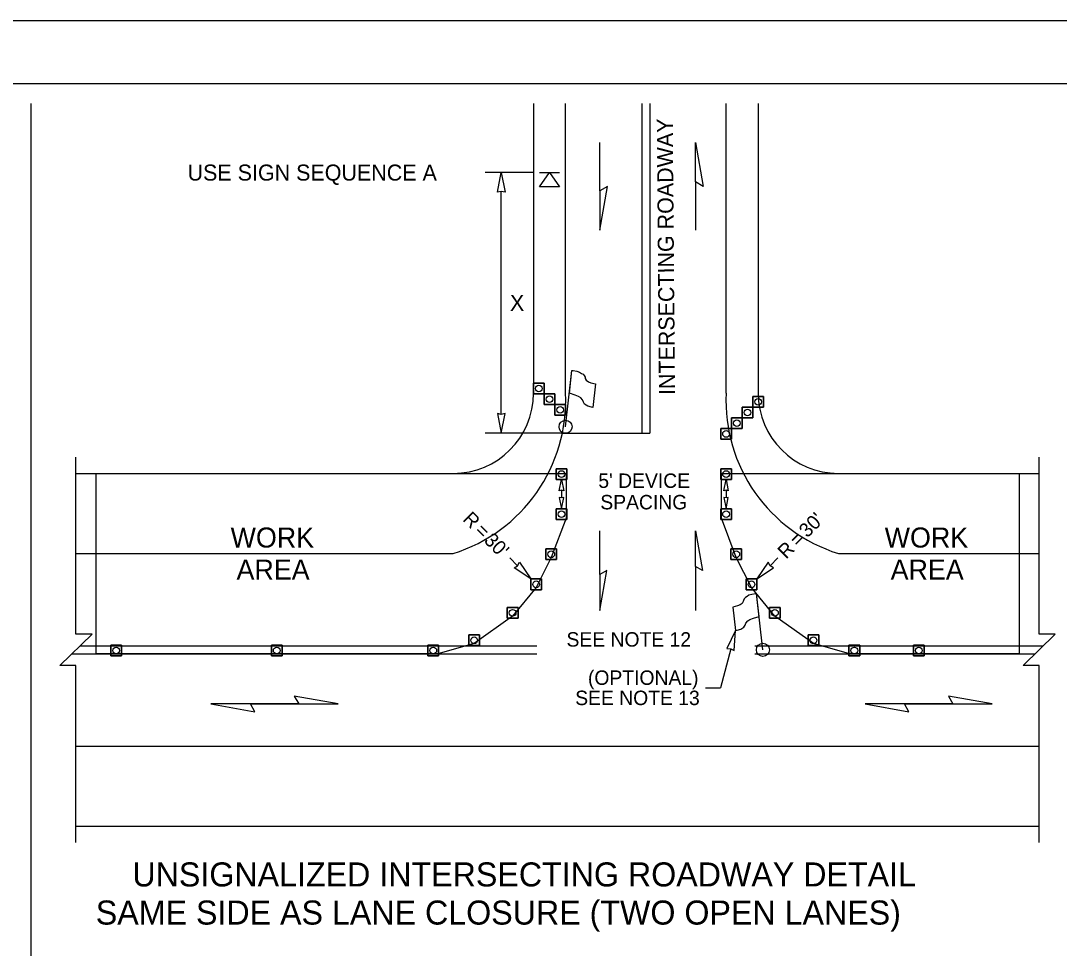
# Model space of a CAD drawing. Extents: x 99999.1 to 100095.7, y 99995 to 100010.7.
# Drawn here: x 100025.2 to 100030.38, y 100006.06 to 100010.69 of the extents above; entities that cross this region are included whole.
import ezdxf

# ---------------------------------------------------------------- set-up
doc = ezdxf.new("R2010")
doc.units = 0
for name, color, linetype in [('RD_ED_ShoulderPavedEdge', 7, 'Continuous'), ('RD_MK_LineDblYellowCenter', 7, 'Continuous'), ('RD_MK_LineEdgeWhite', 7, 'Continuous'), ('RD_MK_LineStop', 7, 'Continuous'), ('SH_DE_DetailBody1Text', 7, 'Continuous'), ('SH_DE_DetailHeading2Text', 7, 'Continuous'), ('SH_GI_PlotLimits', 7, 'Continuous'), ('SH_GI_SheetBorder', 7, 'Continuous'), ('TR_WZ_FlaggingStation', 7, 'Continuous'), ('TR_WZ_PortableSignMountBlk-Org', 7, 'Continuous'), ('TR_WZ_TrafficCone', 7, 'Continuous'), ('TR_WZ_WorkAreaLabel', 7, 'Continuous'), ('TR_WZ_WorkZoneDetails', 7, 'Continuous'), ('TR_WZ_WorkZoneTextCurrent', 7, 'Continuous')]:
    doc.layers.add(name, color=color, linetype=linetype)

msp = doc.modelspace()

# ---------------------------------------------------------------- linework, layer by layer
at = {"layer": 'RD_ED_ShoulderPavedEdge'}
for p, q in [((100025.475, 100008.4304), (100027.355, 100008.4304)), ((100029.275, 100008.4304), (100030.275, 100008.4304)), ((100025.475, 100006.6704), (100030.275, 100006.6704))]:
    msp.add_line(p, q, dxfattribs=at)
for points in [[(100027.755, 100010.275), (100027.755, 100008.8304)], [(100028.875, 100010.275), (100028.875, 100008.8304)]]:
    msp.add_lwpolyline(points, dxfattribs=at)
for centre, start, end in [((100027.355, 100008.8304), 270, 0), ((100029.275, 100008.8304), 180, 270)]:
    msp.add_arc(centre, 0.4, start, end, dxfattribs=at)
at = {"layer": 'RD_MK_LineDblYellowCenter'}
for p, q in [((100028.295, 100010.275), (100028.295, 100008.6304)), ((100028.335, 100010.275), (100028.335, 100008.6304)), ((100025.4957, 100007.5704), (100027.7712, 100007.5704)), ((100028.8588, 100007.5704), (100030.2957, 100007.5704)), ((100025.4543, 100007.5305), (100027.7712, 100007.5305)), ((100028.8588, 100007.5305), (100030.2543, 100007.5305))]:
    msp.add_line(p, q, dxfattribs=at)
at = {"layer": 'RD_MK_LineEdgeWhite'}
for p, q in [((100027.915, 100008.8304), (100027.915, 100010.275)), ((100028.715, 100008.8304), (100028.715, 100010.275)), ((100025.475, 100008.0305), (100027.355, 100008.0305)), ((100029.275, 100008.0305), (100030.275, 100008.0305)), ((100025.475, 100007.0704), (100030.275, 100007.0704))]:
    msp.add_line(p, q, dxfattribs=at)
for centre, start, end in [((100027.1158, 100008.7939), 287.3948, 2.6212), ((100029.5142, 100008.7939), 177.3788, 252.6052)]:
    msp.add_arc(centre, 0.8, start, end, dxfattribs=at)
at = {"layer": 'RD_MK_LineStop'}
msp.add_line((100027.899, 100008.6304), (100028.335, 100008.6304), dxfattribs=at)
at = {"layer": 'SH_GI_PlotLimits'}
msp.add_lwpolyline([(100019.0625, 99999.6875), (100036.0625, 99999.6875), (100036.0625, 100010.6875), (100019.0625, 100010.6875)], close=True, dxfattribs=at)
at = {"layer": 'SH_GI_SheetBorder'}
msp.add_line((100020, 100010.375), (100035.75, 100010.375), dxfattribs=at)
at = {"layer": 'TR_WZ_FlaggingStation'}
for p, q in [((100027.915, 100008.6629), (100027.9471, 100008.9439)), ((100027.934, 100008.8299), (100027.9471, 100008.9442)), ((100028.065, 100008.8764), (100028.0517, 100008.7592)), ((100027.934, 100008.8299), (100027.934, 100008.8299)), ((100028.8797, 100007.7174), (100028.8667, 100007.8317)), ((100028.8988, 100007.5504), (100028.8667, 100007.8314)), ((100028.7487, 100007.7639), (100028.762, 100007.6467)), ((100028.8797, 100007.7174), (100028.8797, 100007.7174))]:
    msp.add_line(p, q, dxfattribs=at)
for points in [[(100027.9471, 100008.9442), (100027.9528, 100008.9429), (100027.9707, 100008.9395), (100027.9845, 100008.9353), (100027.9942, 100008.9292), (100028.0027, 100008.9245), (100028.0084, 100008.9177), (100028.0126, 100008.9098), (100028.0131, 100008.9037), (100028.0185, 100008.8944), (100028.0293, 100008.887), (100028.0417, 100008.8818), (100028.065, 100008.8764)], [(100028.0517, 100008.7592), (100028.0436, 100008.7606), (100028.0259, 100008.7653), (100028.0103, 100008.7758), (100028.0037, 100008.7863), (100027.9998, 100008.7966), (100027.9907, 100008.8075), (100027.9798, 100008.8137), (100027.9624, 100008.8208), (100027.934, 100008.8299)], [(100028.8667, 100007.8317), (100028.8609, 100007.8304), (100028.8431, 100007.827), (100028.8293, 100007.8228), (100028.8196, 100007.8167), (100028.8111, 100007.812), (100028.8054, 100007.8052), (100028.8012, 100007.7973), (100028.8006, 100007.7912), (100028.7953, 100007.7819), (100028.7845, 100007.7745), (100028.7721, 100007.7693), (100028.7487, 100007.7639)], [(100028.762, 100007.6467), (100028.7702, 100007.6481), (100028.7879, 100007.6528), (100028.8035, 100007.6633), (100028.81, 100007.6738), (100028.814, 100007.6841), (100028.823, 100007.695), (100028.834, 100007.7012), (100028.8514, 100007.7083), (100028.8797, 100007.7174)]]:
    msp.add_lwpolyline(points, dxfattribs=at)
for centre in [(100027.915, 100008.6629), (100028.8988, 100007.5504)]:
    msp.add_circle(centre, 0.0325, dxfattribs=at)
at = {"layer": 'TR_WZ_PortableSignMountBlk-Org'}
msp.add_line((100027.785, 100009.9304), (100027.885, 100009.9304), dxfattribs=at)
msp.add_lwpolyline([(100027.8349, 100009.9304), (100027.885, 100009.8586), (100027.785, 100009.8586)], close=True, dxfattribs=at)
at = {"layer": 'TR_WZ_TrafficCone'}
for points in [[(100027.8083, 100008.8803), (100027.8083, 100008.827), (100027.755, 100008.827), (100027.755, 100008.8803), (100027.8083, 100008.8803)], [(100027.755, 100008.8803), (100027.755, 100008.827), (100027.8083, 100008.827), (100027.8083, 100008.8803), (100027.755, 100008.8803)], [(100027.8617, 100008.827), (100027.8617, 100008.7736), (100027.8083, 100008.7736), (100027.8083, 100008.827), (100027.8617, 100008.827)], [(100027.8083, 100008.827), (100027.8083, 100008.7736), (100027.8617, 100008.7736), (100027.8617, 100008.827), (100027.8083, 100008.827)], [(100028.9016, 100008.8138), (100028.8483, 100008.8138), (100028.8483, 100008.7605), (100028.9016, 100008.7605), (100028.9016, 100008.8138)], [(100028.9016, 100008.7605), (100028.8483, 100008.7605), (100028.8483, 100008.8138), (100028.9016, 100008.8138), (100028.9016, 100008.7605)], [(100027.915, 100008.7736), (100027.915, 100008.7203), (100027.8617, 100008.7203), (100027.8617, 100008.7736), (100027.915, 100008.7736)], [(100027.8617, 100008.7736), (100027.8617, 100008.7203), (100027.915, 100008.7203), (100027.915, 100008.7736), (100027.8617, 100008.7736)], [(100028.8483, 100008.7605), (100028.795, 100008.7605), (100028.795, 100008.7071), (100028.8483, 100008.7071), (100028.8483, 100008.7605)], [(100028.8483, 100008.7071), (100028.795, 100008.7071), (100028.795, 100008.7605), (100028.8483, 100008.7605), (100028.8483, 100008.7071)], [(100028.795, 100008.7071), (100028.7416, 100008.7071), (100028.7416, 100008.6538), (100028.795, 100008.6538), (100028.795, 100008.7071)], [(100028.795, 100008.6538), (100028.7416, 100008.6538), (100028.7416, 100008.7071), (100028.795, 100008.7071), (100028.795, 100008.6538)], [(100028.7416, 100008.6538), (100028.6883, 100008.6538), (100028.6883, 100008.6005), (100028.7416, 100008.6005), (100028.7416, 100008.6538)], [(100028.7416, 100008.6005), (100028.6883, 100008.6005), (100028.6883, 100008.6538), (100028.7416, 100008.6538), (100028.7416, 100008.6005)], [(100027.8684, 100008.4538), (100027.9217, 100008.4538), (100027.9217, 100008.4005), (100027.8684, 100008.4005), (100027.8684, 100008.4538)], [(100027.8684, 100008.4005), (100027.9217, 100008.4005), (100027.9217, 100008.4538), (100027.8684, 100008.4538), (100027.8684, 100008.4005)], [(100028.7416, 100008.4538), (100028.6883, 100008.4538), (100028.6883, 100008.4005), (100028.7416, 100008.4005), (100028.7416, 100008.4538)], [(100028.7416, 100008.4005), (100028.6883, 100008.4005), (100028.6883, 100008.4538), (100028.7416, 100008.4538), (100028.7416, 100008.4005)], [(100027.8684, 100008.2538), (100027.9217, 100008.2538), (100027.9217, 100008.2005), (100027.8684, 100008.2005), (100027.8684, 100008.2538)], [(100027.8684, 100008.2005), (100027.9217, 100008.2005), (100027.9217, 100008.2538), (100027.8684, 100008.2538), (100027.8684, 100008.2005)], [(100028.7416, 100008.2538), (100028.6883, 100008.2538), (100028.6883, 100008.2005), (100028.7416, 100008.2005), (100028.7416, 100008.2538)], [(100028.7416, 100008.2005), (100028.6883, 100008.2005), (100028.6883, 100008.2538), (100028.7416, 100008.2538), (100028.7416, 100008.2005)], [(100027.8173, 100008.0538), (100027.8707, 100008.0538), (100027.8707, 100008.0005), (100027.8173, 100008.0005), (100027.8173, 100008.0538)], [(100027.8173, 100008.0005), (100027.8707, 100008.0005), (100027.8707, 100008.0538), (100027.8173, 100008.0538), (100027.8173, 100008.0005)], [(100028.7927, 100008.0538), (100028.7393, 100008.0538), (100028.7393, 100008.0005), (100028.7927, 100008.0005), (100028.7927, 100008.0538)], [(100028.7927, 100008.0005), (100028.7393, 100008.0005), (100028.7393, 100008.0538), (100028.7927, 100008.0538), (100028.7927, 100008.0005)], [(100027.7417, 100007.9038), (100027.795, 100007.9038), (100027.795, 100007.8505), (100027.7417, 100007.8505), (100027.7417, 100007.9038)], [(100027.7417, 100007.8505), (100027.795, 100007.8505), (100027.795, 100007.9038), (100027.7417, 100007.9038), (100027.7417, 100007.8505)], [(100028.8683, 100007.9038), (100028.815, 100007.9038), (100028.815, 100007.8505), (100028.8683, 100007.8505), (100028.8683, 100007.9038)], [(100028.8683, 100007.8505), (100028.815, 100007.8505), (100028.815, 100007.9038), (100028.8683, 100007.9038), (100028.8683, 100007.8505)], [(100027.6247, 100007.7615), (100027.6781, 100007.7615), (100027.6781, 100007.7082), (100027.6247, 100007.7082), (100027.6247, 100007.7615)], [(100027.6247, 100007.7082), (100027.6781, 100007.7082), (100027.6781, 100007.7615), (100027.6247, 100007.7615), (100027.6247, 100007.7082)], [(100028.9853, 100007.7615), (100028.9319, 100007.7615), (100028.9319, 100007.7082), (100028.9853, 100007.7082), (100028.9853, 100007.7615)], [(100028.9853, 100007.7082), (100028.9319, 100007.7082), (100028.9319, 100007.7615), (100028.9853, 100007.7615), (100028.9853, 100007.7082)], [(100027.433, 100007.6247), (100027.4864, 100007.6247), (100027.4864, 100007.5714), (100027.433, 100007.5714), (100027.433, 100007.6247)], [(100027.433, 100007.5714), (100027.4864, 100007.5714), (100027.4864, 100007.6247), (100027.433, 100007.6247), (100027.433, 100007.5714)], [(100029.177, 100007.6247), (100029.1236, 100007.6247), (100029.1236, 100007.5714), (100029.177, 100007.5714), (100029.177, 100007.6247)], [(100029.177, 100007.5714), (100029.1236, 100007.5714), (100029.1236, 100007.6247), (100029.177, 100007.6247), (100029.177, 100007.5714)], [(100025.649, 100007.5738), (100025.7024, 100007.5738), (100025.7024, 100007.5205), (100025.649, 100007.5205), (100025.649, 100007.5738)], [(100025.649, 100007.5205), (100025.7024, 100007.5205), (100025.7024, 100007.5738), (100025.649, 100007.5738), (100025.649, 100007.5205)], [(100026.449, 100007.5738), (100026.5024, 100007.5738), (100026.5024, 100007.5205), (100026.449, 100007.5205), (100026.449, 100007.5738)], [(100026.449, 100007.5205), (100026.5024, 100007.5205), (100026.5024, 100007.5738), (100026.449, 100007.5738), (100026.449, 100007.5205)], [(100027.229, 100007.5738), (100027.2824, 100007.5738), (100027.2824, 100007.5205), (100027.229, 100007.5205), (100027.229, 100007.5738)], [(100027.229, 100007.5205), (100027.2824, 100007.5205), (100027.2824, 100007.5738), (100027.229, 100007.5738), (100027.229, 100007.5205)], [(100029.381, 100007.5738), (100029.3276, 100007.5738), (100029.3276, 100007.5205), (100029.381, 100007.5205), (100029.381, 100007.5738)], [(100029.381, 100007.5205), (100029.3276, 100007.5205), (100029.3276, 100007.5738), (100029.381, 100007.5738), (100029.381, 100007.5205)], [(100029.649, 100007.5738), (100029.7024, 100007.5738), (100029.7024, 100007.5205), (100029.649, 100007.5205), (100029.649, 100007.5738)], [(100029.649, 100007.5205), (100029.7024, 100007.5205), (100029.7024, 100007.5738), (100029.649, 100007.5738), (100029.649, 100007.5205)]]:
    msp.add_lwpolyline(points, dxfattribs=at)
for centre in [(100027.7817, 100008.8536), (100027.835, 100008.8003), (100028.875, 100008.7871), (100027.8883, 100008.747), (100028.8216, 100008.7338), (100028.7683, 100008.6805), (100028.715, 100008.6271), (100027.895, 100008.4271), (100028.715, 100008.4271), (100027.895, 100008.2271), (100028.715, 100008.2271), (100027.844, 100008.0271), (100028.766, 100008.0271), (100027.7683, 100007.8771), (100028.8417, 100007.8771), (100027.6514, 100007.7349), (100028.9586, 100007.7349), (100027.4597, 100007.598), (100029.1503, 100007.598), (100025.6757, 100007.5471), (100026.4757, 100007.5471), (100027.2557, 100007.5471), (100029.3543, 100007.5471), (100029.6757, 100007.5471)]:
    msp.add_circle(centre, 0.0167, dxfattribs=at)
at = {"layer": 'TR_WZ_WorkZoneDetails'}
for p, q in [((100025.25, 100010.275), (100025.25, 100001.6859)), ((100028.0855, 100009.8393), (100028.0855, 100010.0804)), ((100027.755, 100009.9304), (100027.515, 100009.9304)), ((100028.5627, 100009.8839), (100028.5627, 100009.6428)), ((100027.595, 100008.7242), (100027.595, 100009.8367)), ((100027.899, 100008.6304), (100027.515, 100008.6304)), ((100027.8951, 100008.3459), (100027.8951, 100008.3083)), ((100028.715, 100008.3459), (100028.715, 100008.3083)), ((100028.0855, 100007.9255), (100028.0855, 100008.1445)), ((100027.6754, 100007.9701), (100027.637, 100008.0085)), ((100028.9346, 100007.9701), (100028.973, 100008.0085)), ((100028.5627, 100007.9659), (100028.5627, 100007.7469)), ((100028.7385, 100007.556), (100028.688, 100007.3613)), ((100028.6118, 100007.3613), (100028.688, 100007.3613)), ((100026.3444, 100007.2805), (100026.5856, 100007.2805)), ((100026.5856, 100007.2805), (100026.3444, 100007.2805)), ((100029.6043, 100007.2805), (100029.8454, 100007.2805)), ((100029.8454, 100007.2805), (100029.6043, 100007.2805))]:
    msp.add_line(p, q, dxfattribs=at)
for points in [[(100028.5627, 100010.0804), (100028.6013, 100009.8616), (100028.5627, 100009.8839)], [(100027.595, 100009.9304), (100027.6143, 100009.8322), (100027.595, 100009.8367), (100027.5757, 100009.8322)], [(100028.0855, 100009.6428), (100028.124, 100009.8616), (100028.0855, 100009.8393)], [(100027.595, 100008.6304), (100027.6143, 100008.7287), (100027.595, 100008.7242), (100027.5757, 100008.7287)], [(100027.9183, 100008.4304), (100027.9183, 100008.2071), (100027.844, 100008.0105), (100027.7683, 100007.8605), (100027.7683, 100007.8605), (100027.7683, 100007.8605), (100027.6514, 100007.7182), (100027.6514, 100007.7182), (100027.6514, 100007.7182), (100027.4597, 100007.5814), (100027.279, 100007.5305), (100026.499, 100007.5305), (100025.699, 100007.5305), (100025.575, 100007.5305), (100025.575, 100008.4304)], [(100027.895, 100008.4005), (100027.9063, 100008.3433), (100027.895, 100008.3459), (100027.8838, 100008.3433)], [(100030.175, 100008.4304), (100030.175, 100007.5305), (100029.699, 100007.5305), (100029.6523, 100007.5305), (100029.6523, 100007.5305), (100029.6523, 100007.5305), (100029.331, 100007.5305), (100029.331, 100007.5305), (100029.331, 100007.5305), (100029.1503, 100007.5814), (100028.9586, 100007.7182), (100028.8417, 100007.8605), (100028.766, 100008.0105), (100028.6917, 100008.2071), (100028.6917, 100008.4304)], [(100028.7149, 100008.4005), (100028.7261, 100008.3433), (100028.7149, 100008.3459), (100028.7037, 100008.3433)], [(100027.8951, 100008.2538), (100027.9063, 100008.3109), (100027.8951, 100008.3083), (100027.8839, 100008.3109)], [(100028.715, 100008.2538), (100028.7262, 100008.3109), (100028.715, 100008.3083), (100028.7037, 100008.3109)], [(100028.5627, 100008.1445), (100028.5977, 100007.9457), (100028.5627, 100007.9659)], [(100027.7417, 100007.9038), (100027.6586, 100007.9597), (100027.6754, 100007.9701), (100027.6858, 100007.987)], [(100028.8683, 100007.9038), (100028.9514, 100007.9597), (100028.9346, 100007.9701), (100028.9242, 100007.987)], [(100028.0855, 100007.7469), (100028.1205, 100007.9457), (100028.0855, 100007.9255)], [(100028.762, 100007.6467), (100028.7187, 100007.5564), (100028.7385, 100007.556), (100028.7561, 100007.5467)], [(100026.7821, 100007.2805), (100026.5633, 100007.319), (100026.5856, 100007.2805)], [(100030.0419, 100007.2805), (100029.8231, 100007.319), (100029.8454, 100007.2805)], [(100026.1479, 100007.2805), (100026.3667, 100007.2419), (100026.3444, 100007.2805)], [(100029.4077, 100007.2805), (100029.6265, 100007.2419), (100029.6043, 100007.2805)]]:
    msp.add_lwpolyline(points, close=True, dxfattribs=at)
for points in [[(100025.475, 100006.5904), (100025.475, 100007.473), (100025.395, 100007.473), (100025.555, 100007.6279), (100025.475, 100007.6279), (100025.475, 100008.5105)], [(100030.275, 100006.5904), (100030.275, 100007.473), (100030.195, 100007.473), (100030.355, 100007.6279), (100030.275, 100007.6279), (100030.275, 100008.5105)]]:
    msp.add_lwpolyline(points, dxfattribs=at)

# ---------------------------------------------------------------- texts
at = {"layer": 'SH_DE_DetailBody1Text'}
msp.add_text('INTERSECTING ROADWAY', height=0.08, rotation=90.4626, dxfattribs=at).set_placement((100028.4607, 100008.8214))
at = {"layer": 'SH_DE_DetailHeading2Text'}
for s, p in [('UNSIGNALIZED INTERSECTING ROADWAY DETAIL', (100025.7563, 100006.3705)), ('SAME SIDE AS LANE CLOSURE (TWO OPEN LANES)', (100025.5738, 100006.1804))]:
    msp.add_text(s, height=0.12, rotation=360, dxfattribs=at).set_placement(p)
at = {"layer": 'TR_WZ_WorkAreaLabel'}
for s, p in [('WORK', (100026.2458, 100008.0605)), ('WORK', (100029.5056, 100008.0605)), ('AREA', (100026.2754, 100007.9004)), ('AREA', (100029.5352, 100007.9004))]:
    msp.add_text(s, height=0.1, dxfattribs=at).set_placement(p)
at = {"layer": 'TR_WZ_WorkZoneTextCurrent'}
for s, height, p in [('USE SIGN SEQUENCE A', 0.08, (100026.0313, 100009.8904)), ('X', 0.08, (100027.6379, 100009.2404)), ("5' DEVICE", 0.072, (100028.0784, 100008.3579)), ('SPACING', 0.072, (100028.0883, 100008.2509)), ('SEE NOTE 12', 0.072, (100027.9199, 100007.5665)), ('(OPTIONAL)', 0.072, (100028.0267, 100007.3757)), ('SEE NOTE 13', 0.072, (100027.9632, 100007.2749))]:
    msp.add_text(s, height=height, dxfattribs=at).set_placement(p)
for s, rotation, p in [('R', 315, (100027.3982, 100008.1977)), ("30'", 45, (100029.1202, 100008.1062)), ('=', 315, (100027.4574, 100008.1386)), ("30'", 315, (100027.5042, 100008.0917)), ('=', 45, (100029.0734, 100008.0593)), ('R', 45, (100029.0142, 100008.0002))]:
    msp.add_text(s, height=0.07, rotation=rotation, dxfattribs=at).set_placement(p)

doc.saveas('drawing.dxf')
